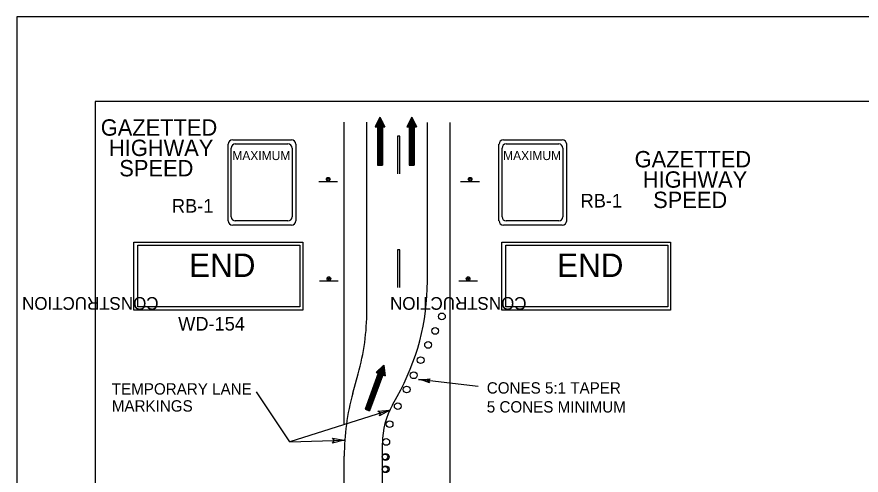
# Model space of a CAD drawing. Extents: x 2157 to 2399, y 147 to 426.
# Drawn here: x 2182.7 to 2290.7, y 367.4 to 426 of the extents above; entities that cross this region are included whole.
import ezdxf

# ---------------------------------------------------------------- set-up
doc = ezdxf.new("R2010")
doc.units = 0
for name, color, linetype in [('Level 10', 7, 'Continuous'), ('Level 2', 7, 'Continuous'), ('Level 44', 7, 'Continuous'), ('Level 5', 7, 'Continuous'), ('Level 60', 7, 'Continuous')]:
    doc.layers.add(name, color=color, linetype=linetype)

# ---------------------------------------------------------------- blocks, each defined once
blk = doc.blocks.new('LT1')
at = {"layer": 'Level 5'}
blk.add_lwpolyline([(0, 0), (-3, -0.62), (-2.504, 0), (-3, 0.62)], close=True, dxfattribs=at)
blk = doc.blocks.new('END')
at = {"layer": 'Level 2'}
for points in [[(0, 8.676), (21.598, 8.676), (21.598, 0), (0, 0)], [(0.511, 8.287), (21.224, 8.287), (21.224, 0.397), (0.511, 0.397)]]:
    blk.add_lwpolyline(points, close=True, dxfattribs=at)
at = {"layer": 'Level 44'}
for s, height, rotation, p in [('END', 3, 359.99999, (7.085, 4.219)), ('CONSTRUCTION', 1.62, 179.99999, (3.164, 1.653))]:
    blk.add_text(s, height=height, rotation=rotation, dxfattribs=at).set_placement(p)
blk = doc.blocks.new('APRNTR')
at = {"layer": 'Level 60'}
for points in [[(19.126, 268.191), (-196.874, 268.191), (-196.874, -10.809), (19.126, -10.809)], [(0, 257.382), (-186.874, 257.382), (-186.874, 0), (0, 0)]]:
    blk.add_lwpolyline(points, close=True, dxfattribs=at)

msp = doc.modelspace()

# ---------------------------------------------------------------- linework, layer by layer
at = {"layer": 'Level 10'}
for p, q in [((2224.59, 373.95), (2224.59, 412.54)), ((2227.49, 388.45), (2227.49, 412.54)), ((2229.16, 413.18), (2228.55, 411.95)), ((2228.86, 412.57), (2228.86, 407.04)), ((2228.93, 412.72), (2228.93, 407.04)), ((2229.01, 412.87), (2229.01, 407.04)), ((2229.09, 413.03), (2229.09, 407.04)), ((2229.16, 413.18), (2229.16, 407.04)), ((2229.16, 413.18), (2229.78, 411.95)), ((2229.24, 413.03), (2229.24, 407.04)), ((2229.32, 412.87), (2229.32, 407.04)), ((2229.39, 412.72), (2229.39, 407.04)), ((2229.47, 412.57), (2229.47, 407.04)), ((2233.23, 413.18), (2232.61, 411.95)), ((2232.92, 412.57), (2232.92, 407.04)), ((2233, 412.72), (2233, 407.04)), ((2233.07, 412.87), (2233.07, 407.04)), ((2233.15, 413.03), (2233.15, 407.04)), ((2233.23, 413.18), (2233.23, 407.04)), ((2233.23, 413.18), (2233.84, 411.95)), ((2233.3, 413.03), (2233.3, 407.04)), ((2233.38, 412.87), (2233.38, 407.04)), ((2233.46, 412.72), (2233.46, 407.04)), ((2233.53, 412.57), (2233.53, 407.04)), ((2228.55, 411.95), (2228.86, 411.95)), ((2228.63, 412.11), (2228.63, 411.95)), ((2228.7, 412.26), (2228.7, 411.95)), ((2228.78, 412.41), (2228.78, 411.95)), ((2228.86, 411.95), (2228.86, 407.04)), ((2229.47, 411.95), (2229.47, 407.04)), ((2229.47, 411.95), (2229.78, 411.95)), ((2229.55, 412.41), (2229.55, 411.95)), ((2229.62, 412.26), (2229.62, 411.95)), ((2229.7, 412.11), (2229.7, 411.95)), ((2232.61, 411.95), (2232.92, 411.95)), ((2232.69, 412.11), (2232.69, 411.95)), ((2232.77, 412.26), (2232.77, 411.95)), ((2232.84, 412.41), (2232.84, 411.95)), ((2232.92, 411.95), (2232.92, 407.04)), ((2233.53, 411.95), (2233.53, 407.04)), ((2233.53, 411.95), (2233.84, 411.95)), ((2233.61, 412.41), (2233.61, 411.95)), ((2233.69, 412.26), (2233.69, 411.95)), ((2233.77, 412.11), (2233.77, 411.95)), ((2235.23, 392.21), (2235.23, 412.51)), ((2238.14, 338.67), (2238.14, 412.51)), ((2231.4, 410.76), (2231.4, 405.92)), ((2231.69, 410.76), (2231.4, 410.76)), ((2231.69, 405.92), (2231.69, 410.76)), ((2228.86, 407.04), (2229.47, 407.04)), ((2232.92, 407.04), (2233.53, 407.04)), ((2231.4, 396.24), (2231.4, 391.4)), ((2231.69, 396.24), (2231.4, 396.24)), ((2231.69, 391.4), (2231.69, 396.24)), ((2229.41, 381.27), (2227.41, 375.79)), ((2229.53, 381.39), (2227.49, 375.77)), ((2229.66, 381.5), (2227.56, 375.74)), ((2229.67, 381.33), (2227.63, 375.71)), ((2229.66, 381.5), (2228.66, 380.56)), ((2229.66, 381.5), (2229.81, 380.14)), ((2225.7, 377.91), (2226.39, 380.38)), ((2229.16, 381.03), (2227.27, 375.84)), ((2228.95, 380.46), (2227.27, 375.84)), ((2229.28, 381.15), (2227.34, 375.82)), ((2229.69, 381.16), (2227.7, 375.69)), ((2229.71, 380.99), (2227.77, 375.66)), ((2229.73, 380.82), (2227.84, 375.63)), ((2229.52, 380.25), (2227.84, 375.63)), ((2228.66, 380.56), (2228.95, 380.46)), ((2228.78, 380.68), (2228.73, 380.53)), ((2228.91, 380.8), (2228.8, 380.51)), ((2229.03, 380.92), (2228.87, 380.48)), ((2229.52, 380.25), (2229.81, 380.14)), ((2229.75, 380.65), (2229.6, 380.22)), ((2229.77, 380.48), (2229.67, 380.19)), ((2229.79, 380.31), (2229.74, 380.17)), ((2241.72, 378.76), (2234.1, 379.65)), ((2235.06, 379.42), (2235.38, 379.38)), ((2235.06, 379.42), (2235.38, 379.38)), ((2235.1, 379.65), (2235.43, 379.62)), ((2235.1, 379.65), (2235.43, 379.62)), ((2217.65, 371.68), (2213.35, 378.08)), ((2230.76, 376.41), (2231.37, 377.48)), ((2227.27, 375.84), (2227.84, 375.63)), ((2230.42, 375.75), (2217.65, 371.68)), ((2217.65, 371.68), (2224.59, 371.89)), ((2229.48, 334.96), (2229.48, 371.5)), ((2224.59, 366.46), (2224.59, 369.84))]:
    msp.add_line(p, q, dxfattribs=at)
for centre, radius in [((2237.09, 387.71), 0.431), ((2236.23, 385.86), 0.431), ((2235.32, 384.07), 0.431), ((2234.37, 382.12), 0.431), ((2233.48, 380.19), 0.431), ((2232.58, 378.37), 0.431), ((2231.44, 376.24), 0.431), ((2230.4, 373.95), 0.431), ((2229.97, 371.67), 0.431), ((2229.81, 369.76), 0.359), ((2229.89, 369.75), 0.431), ((2229.81, 368.18), 0.359), ((2229.89, 368.18), 0.431)]:
    msp.add_circle(centre, radius, dxfattribs=at)
for centre, radius, start, end in [((2205.23, 392.21), 30, 330.6023, 0), ((2197.49, 388.45), 30, 344.3937, 0), ((2234.44, 387.94), 8.3, 267.6856, 277.8526), ((2234.44, 387.94), 8.3, 267.6856, 277.8526), ((2232.38, 371.11), 8.71, 68.9358, 78.6135), ((2232.38, 371.11), 8.71, 68.9358, 78.6135), ((2235.72, 379.46), 0.303, 119.9121, 226.4002), ((2235.72, 379.46), 0.303, 119.9121, 226.4002), ((2254.59, 369.84), 30, 164.3937, 180), ((2239.48, 371.5), 10, 150.6023, 180)]:
    msp.add_arc(centre, radius, start, end, dxfattribs=at)
at = {"layer": 'Level 2'}
for points in [[(2197.68, 397.2), (2219.28, 397.2), (2219.28, 388.53), (2197.68, 388.53)], [(2198.19, 396.81), (2218.9, 396.81), (2218.9, 388.92), (2198.19, 388.92)], [(2244.75, 397.2), (2266.35, 397.2), (2266.35, 388.53), (2244.75, 388.53)], [(2245.26, 396.81), (2265.97, 396.81), (2265.97, 388.92), (2245.26, 388.92)]]:
    msp.add_lwpolyline(points, close=True, dxfattribs=at)
at = {"layer": 'Level 44'}
for p, q in [((2209.75, 399.94), (2209.75, 409.71)), ((2210.33, 410.29), (2217.83, 410.29)), ((2210.66, 409.75), (2217.4, 409.75)), ((2218.41, 409.71), (2218.41, 399.94)), ((2244.39, 399.94), (2244.39, 409.71)), ((2244.97, 410.29), (2252.47, 410.29)), ((2245.3, 409.75), (2252.04, 409.75)), ((2253.04, 409.71), (2253.04, 399.94)), ((2210.14, 400.43), (2210.14, 409.23)), ((2217.93, 409.23), (2217.93, 400.43)), ((2244.78, 400.43), (2244.78, 409.23)), ((2252.57, 409.23), (2252.57, 400.43)), ((2221.34, 404.97), (2223.74, 404.97)), ((2239.48, 404.97), (2241.88, 404.97)), ((2209.75, 399.94), (2209.75, 399.94)), ((2210.14, 400.43), (2210.14, 400.43)), ((2217.4, 399.91), (2210.66, 399.91)), ((2244.39, 399.94), (2244.39, 399.94)), ((2244.78, 400.43), (2244.78, 400.43)), ((2252.04, 399.91), (2245.3, 399.91)), ((2217.83, 399.36), (2210.33, 399.36)), ((2252.47, 399.36), (2244.97, 399.36)), ((2221.43, 392.26), (2223.82, 392.26)), ((2239.24, 392.26), (2241.64, 392.26))]:
    msp.add_line(p, q, dxfattribs=at)
for centre, radius in [((2222.55, 405.24), 0.24), ((2222.55, 405.24), 0.12), ((2240.69, 405.24), 0.24), ((2240.69, 405.24), 0.12), ((2222.63, 392.53), 0.24), ((2222.63, 392.53), 0.12), ((2240.44, 392.53), 0.24), ((2240.44, 392.53), 0.12)]:
    msp.add_circle(centre, radius, dxfattribs=at)
for centre, radius, start, end in [((2210.33, 409.71), 0.578, 90, 180), ((2210.66, 409.23), 0.52, 90, 180), ((2217.4, 409.23), 0.52, 360, 90), ((2217.83, 409.71), 0.578, 360, 90), ((2244.97, 409.71), 0.578, 90, 180), ((2245.3, 409.23), 0.52, 90, 180), ((2252.04, 409.23), 0.52, 360, 90), ((2252.47, 409.71), 0.578, 360, 90), ((2210.33, 399.94), 0.578, 180, 270), ((2210.66, 400.43), 0.52, 180, 270), ((2217.4, 400.43), 0.52, 270, 360), ((2217.83, 399.94), 0.578, 270, 360), ((2244.97, 399.94), 0.578, 180, 270), ((2245.3, 400.43), 0.52, 180, 270), ((2252.04, 400.43), 0.52, 270, 360), ((2252.47, 399.94), 0.578, 270, 360)]:
    msp.add_arc(centre, radius, start, end, dxfattribs=at)

# ---------------------------------------------------------------- block references
at = {"layer": 'Level 10'}
msp.add_blockref('APRNTR', (2379.59, 157.8), dxfattribs=at)
at = {"layer": 'Level 2'}
for p in [(2197.68, 388.53), (2244.75, 388.53)]:
    msp.add_blockref('END', p, dxfattribs=at)
at = {"layer": 'Level 5', "xscale": 0.5}
for p, yscale, rotation in [((2230.42, 375.75), 0.5000000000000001, 17.68769606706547), ((2224.59, 371.88), 0.5, 1.7164611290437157)]:
    msp.add_blockref('LT1', p, dxfattribs=dict(at, yscale=yscale, rotation=rotation))

# ---------------------------------------------------------------- texts
at = {"layer": 'Level 10'}
for s, height, p in [('GAZETTED', 2.09, (2193.45, 410.81)), ('HIGHWAY', 2.09, (2194.5, 408.21)), ('GAZETTED', 2.09, (2261.74, 406.76)), ('SPEED', 2.09, (2195.82, 405.61)), ('HIGHWAY', 2.09, (2262.79, 404.16)), ('RB-1', 1.742, (2254.83, 401.63)), ('SPEED', 2.09, (2264.11, 401.56)), ('RB-1', 1.742, (2202.55, 400.97)), ('WD-154', 1.742, (2203.35, 385.9)), ('CONES 5:1 TAPER', 1.4514, (2242.83, 377.85)), ('5 CONES MINIMUM', 1.4514, (2242.83, 375.43))]:
    msp.add_text(s, height=height, dxfattribs=at).set_placement(p)
at = {"layer": 'Level 44'}
for s, height, rotation, p in [('MAXIMUM', 1.147, 360, (2210.28, 407.69)), ('MAXIMUM', 1.147, 360, (2244.92, 407.69)), ('CONSTRUCTION', 1.6202, 180, (2200.84, 390.18)), ('CONSTRUCTION', 1.6202, 180, (2247.91, 390.18))]:
    msp.add_text(s, height=height, rotation=rotation, dxfattribs=at).set_placement(p)
at = {"layer": 'Level 5'}
for s, height, p in [('TEMPORARY LANE', 1.4514, (2194.86, 377.72)), ('MARKINGS', 1.451, (2194.86, 375.55))]:
    msp.add_text(s, height=height, dxfattribs=at).set_placement(p)

doc.saveas('drawing.dxf')
